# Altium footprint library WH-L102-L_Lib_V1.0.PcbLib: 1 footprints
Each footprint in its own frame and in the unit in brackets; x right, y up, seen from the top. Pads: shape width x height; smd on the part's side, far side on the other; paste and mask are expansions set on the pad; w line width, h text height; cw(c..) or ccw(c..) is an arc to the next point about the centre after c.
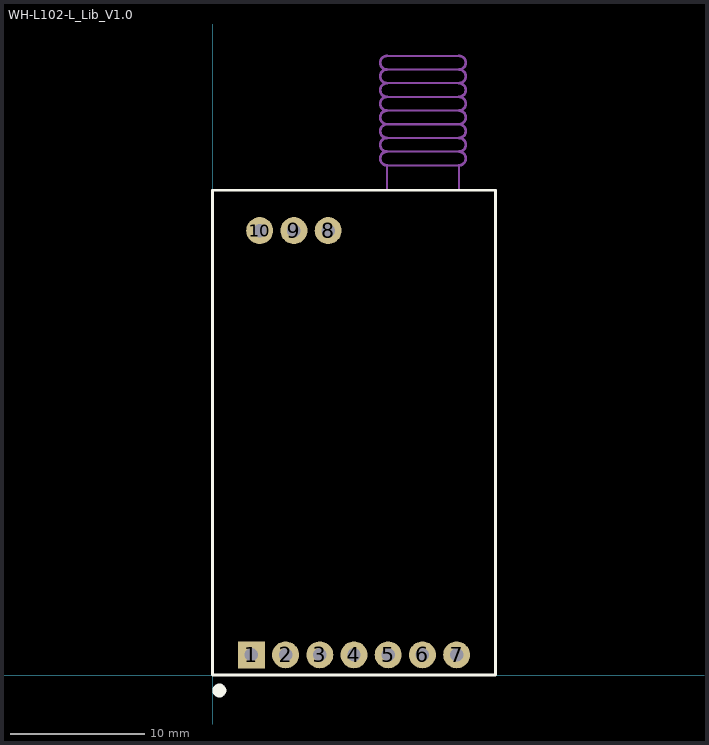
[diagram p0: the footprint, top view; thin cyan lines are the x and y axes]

## WH-L102-L_Lib_V1.0 [mm]
pads (10):
  rect 2x2 hole 1: 1(2.88,1.5)
  round 2 hole 1: 2(5.42,1.5) 3(7.96,1.5) 4(10.5,1.5) 5(13.04,1.5) 6(15.58,1.5) 7(18.12,1.5) 8(8.58,33) 9(6.04,33) 10(3.5,33)
Top Overlay:
  circle w0.762: c0.508,-1.143 r0.127
  lines w0.2: 0,0 0,36 21,36 21,0 0,0
Mechanical 5:
  lines w0.152: 12.954,36 12.954,37.846 18.288,37.846 18.288,36 ; 12.954,38.862 18.288,38.862 ; 12.954,39.878 18.288,39.878 ; 12.954,40.894 18.288,40.894 ; 12.954,41.91 18.288,41.91 ; 12.954,42.926 18.288,42.926 ; 12.954,43.942 18.288,43.942 ; 12.954,44.958 18.288,44.958 ; 12.954,45.974 18.288,45.974
  lines w0.203: 12.954,37.846 cw(c12.954,38.354) 12.954,38.862 cw(c12.954,39.37) 12.954,39.878 cw(c12.954,40.386) 12.954,40.894 cw(c12.954,41.402) 12.954,41.91 cw(c12.954,42.418) 12.954,42.926 cw(c12.954,43.434) 12.954,43.942 cw(c12.954,44.45) 12.954,44.958 cw(c12.954,45.466) 12.954,45.974 ; 18.288,37.846 ccw(c18.288,38.354) 18.288,38.862 ccw(c18.288,39.37) 18.288,39.878 ccw(c18.288,40.386) 18.288,40.894 ccw(c18.288,41.402) 18.288,41.91 ccw(c18.288,42.418) 18.288,42.926 ccw(c18.288,43.434) 18.288,43.942 ccw(c18.288,44.45) 18.288,44.958 ccw(c18.288,45.466) 18.288,45.974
